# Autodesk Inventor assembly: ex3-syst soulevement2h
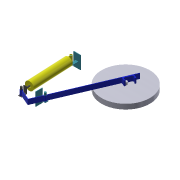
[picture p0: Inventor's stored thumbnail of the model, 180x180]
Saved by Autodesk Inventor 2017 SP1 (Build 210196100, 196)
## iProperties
Part Number: ex3-syst soulevement2h
Material: Générique
Document SubType Name: Assembly
Designer: TJ
Author: TJ
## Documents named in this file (6)
- H:\Consmec\TSsi\02-Cours\02-02-Cinematique\02-02-02-Cinematique graphique\02-02-02-03-Composition des Vitesses\02-02-02-03-02-Exercices compo des Vitesses\02-02-02-03-02-03-Exercice3CompVit\ex3-syst soulevement2h.iam
- H:\Consmec\TSsi\02-Cours\02-02-Cinematique\02-02-02-Cinematique graphique\02-02-02-03-Composition des Vitesses\02-02-02-03-02-Exercices compo des Vitesses\02-02-02-03-02-03-Exercice3CompVit\Pièce5.ipt
- H:\Consmec\TSsi\02-Cours\02-02-Cinematique\02-02-02-Cinematique graphique\02-02-02-03-Composition des Vitesses\02-02-02-03-02-Exercices compo des Vitesses\02-02-02-03-02-03-Exercice3CompVit\Pièce3.ipt
- H:\Consmec\TSsi\02-Cours\02-02-Cinematique\02-02-02-Cinematique graphique\02-02-02-03-Composition des Vitesses\02-02-02-03-02-Exercices compo des Vitesses\02-02-02-03-02-03-Exercice3CompVit\Pièce4.ipt
- H:\Consmec\TSsi\02-Cours\02-02-Cinematique\02-02-02-Cinematique graphique\02-02-02-03-Composition des Vitesses\02-02-02-03-02-Exercices compo des Vitesses\02-02-02-03-02-03-Exercice3CompVit\Pièce2.ipt
- H:\Consmec\TSsi\02-Cours\02-02-Cinematique\02-02-02-Cinematique graphique\02-02-02-03-Composition des Vitesses\02-02-02-03-02-Exercices compo des Vitesses\02-02-02-03-02-03-Exercice3CompVit\Pièce1.ipt
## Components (6 placed, 5 different names)
1. Pièce5:1 — Logement:1, Angle:2, Angle:3
2. Pièce5:2 — Logement:3, Angle:3
3. Pièce3:1 — Logement:1, Placage:1, Angle:1
4. Pièce4:1 — Placage:1, Angle:1, Logement:2, Angle:2
5. Pièce2:1 — Logement:2, Logement:3, Logement:4
6. Pièce1:1 — Logement:4
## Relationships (8: Insert 4, Angle 3, Mate 1)
- Logement:1 [Insert]: Pièce5:1 ↔ Pièce3:1
- Placage:1 [Mate]: Pièce3:1 ↔ Pièce4:1
- Angle:1: Pièce3:1 ↔ Pièce4:1
- Logement:2 [Insert]: Pièce4:1 ↔ Pièce2:1
- Angle:2: Pièce5:1 ↔ Pièce4:1
- Logement:3 [Insert]: Pièce5:2 ↔ Pièce2:1
- Angle:3: Pièce5:1 ↔ Pièce5:2
- Logement:4 [Insert]: Pièce2:1 ↔ Pièce1:1
